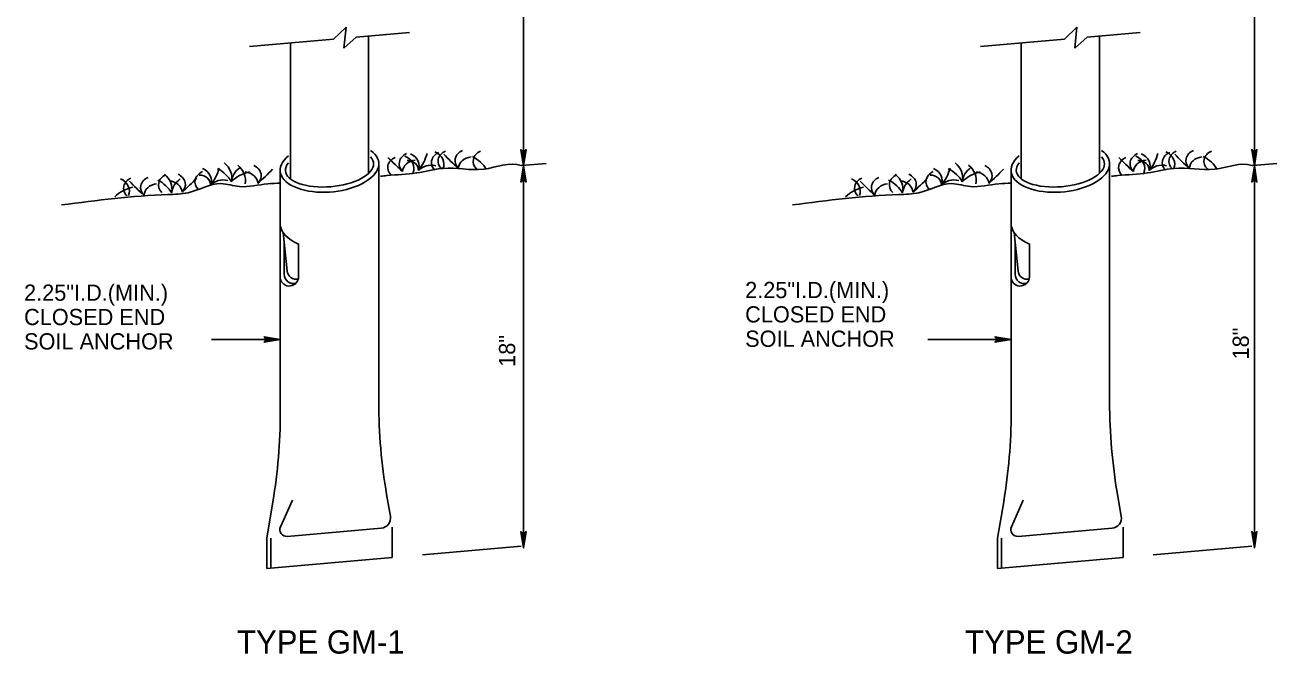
# Model space of a CAD drawing. Extents: x 640253 to 641999, y 298458 to 299646.
# Drawn here: x 640658.7 to 640890, y 299353.4 to 299469.6 of the extents above; entities that cross this region are included whole.
import ezdxf

# ---------------------------------------------------------------- set-up
doc = ezdxf.new("R2010")
doc.units = 0
doc.layers.add('2', color=7, linetype='Continuous')

msp = doc.modelspace()

# ---------------------------------------------------------------- linework, layer by layer
at = {"layer": '2'}
for p, q in [((640750.8, 299443.58), (640750.8, 299512.4)), ((640885.87, 299443.58), (640885.87, 299512.4)), ((640715.71, 299466.98), (640718.01, 299469.2)), ((640718.01, 299469.2), (640717.61, 299465.31)), ((640850.79, 299466.98), (640853.09, 299469.2)), ((640853.09, 299469.2), (640852.69, 299465.31)), ((640700.17, 299465.61), (640715.71, 299466.98)), ((640717.61, 299465.31), (640719.88, 299467.35)), ((640719.88, 299467.35), (640729.7, 299468.21)), ((640722.17, 299467.55), (640722.17, 299442.19)), ((640835.25, 299465.61), (640850.79, 299466.98)), ((640852.69, 299465.31), (640854.96, 299467.35)), ((640854.96, 299467.35), (640864.78, 299468.21)), ((640857.25, 299467.55), (640857.25, 299442.19)), ((640707.71, 299466.28), (640707.71, 299441.18)), ((640842.79, 299466.28), (640842.79, 299441.18)), ((640724.04, 299444.16), (640724.04, 299399.89)), ((640750.5, 299443.61), (640754.97, 299444)), ((640750.8, 299373), (640750.8, 299443.58)), ((640859.12, 299444.16), (640859.12, 299399.89)), ((640885.57, 299443.61), (640890.05, 299444)), ((640885.87, 299373), (640885.87, 299443.58)), ((640705.85, 299442.57), (640705.85, 299398.05)), ((640840.92, 299442.57), (640840.92, 299398.05)), ((640707.11, 299424.14), (640706.38, 299431.28)), ((640842.19, 299424.14), (640841.45, 299431.28)), ((640706.58, 299429.29), (640706.58, 299423.53)), ((640709.23, 299429.14), (640709.23, 299423.08)), ((640841.66, 299429.29), (640841.66, 299423.53)), ((640844.31, 299429.14), (640844.31, 299423.08)), ((640693.12, 299411.48), (640705.85, 299411.48)), ((640825.54, 299411.48), (640840.92, 299411.48)), ((640703.35, 299374.8), (640704.47, 299381.53)), ((640705.88, 299376.89), (640708.08, 299381.83)), ((640726.2, 299378.84), (640725.5, 299382.86)), ((640838.42, 299374.8), (640839.55, 299381.53)), ((640840.96, 299376.89), (640843.16, 299381.83)), ((640861.27, 299378.84), (640860.58, 299382.86)), ((640707.13, 299375.13), (640724.51, 299376.66)), ((640726.54, 299376.84), (640726.54, 299371.21)), ((640842.21, 299375.13), (640859.59, 299376.66)), ((640861.62, 299376.84), (640861.62, 299371.21)), ((640703.35, 299374.8), (640703.35, 299369.18)), ((640704.1, 299374.8), (640704.1, 299369.18)), ((640838.42, 299374.8), (640838.42, 299369.18)), ((640839.17, 299374.8), (640839.17, 299369.18)), ((640732.12, 299371.7), (640750.34, 299373.3)), ((640867.2, 299371.7), (640885.42, 299373.3)), ((640703.35, 299369.18), (640726.54, 299371.21)), ((640838.42, 299369.18), (640861.62, 299371.21))]:
    msp.add_line(p, q, dxfattribs=at)
for points in [[(640751.15, 299446.43), (640750.95, 299446.33), (640750.8, 299443.58), (640751.15, 299446.43), (640751.28, 299446.58), (640750.8, 299443.58), (640750.66, 299446.33), (640750.46, 299446.43), (640750.8, 299443.58), (640750.32, 299446.58), (640750.46, 299446.43)], [(640886.23, 299446.43), (640886.03, 299446.33), (640885.87, 299443.58), (640886.23, 299446.43), (640886.36, 299446.58), (640885.87, 299443.58), (640885.74, 299446.33), (640885.54, 299446.43), (640885.87, 299443.58), (640885.4, 299446.58), (640885.54, 299446.43)], [(640750.44, 299440.73), (640750.64, 299440.83), (640750.8, 299443.58), (640750.44, 299440.73), (640750.31, 299440.58), (640750.8, 299443.58), (640750.93, 299440.83), (640751.14, 299440.73), (640750.8, 299443.58), (640751.27, 299440.58), (640751.14, 299440.73)], [(640885.52, 299440.73), (640885.72, 299440.83), (640885.87, 299443.58), (640885.52, 299440.73), (640885.39, 299440.58), (640885.87, 299443.58), (640886.01, 299440.83), (640886.21, 299440.73), (640885.87, 299443.58), (640886.35, 299440.58), (640886.21, 299440.73)], [(640702.99, 299411.84), (640703.1, 299411.63), (640705.85, 299411.48), (640702.99, 299411.84), (640702.85, 299411.97), (640705.85, 299411.48), (640703.1, 299411.35), (640703, 299411.14), (640705.85, 299411.48), (640702.85, 299411.01), (640703, 299411.14)], [(640838.07, 299411.84), (640838.18, 299411.63), (640840.92, 299411.48), (640838.07, 299411.84), (640837.92, 299411.97), (640840.92, 299411.48), (640838.18, 299411.35), (640838.08, 299411.14), (640840.92, 299411.48), (640837.92, 299411.01), (640838.08, 299411.14)], [(640751.15, 299375.85), (640750.95, 299375.75), (640750.8, 299373), (640751.15, 299375.85), (640751.28, 299376), (640750.8, 299373), (640750.66, 299375.75), (640750.46, 299375.85), (640750.8, 299373), (640750.32, 299376), (640750.46, 299375.85)], [(640886.23, 299375.85), (640886.03, 299375.75), (640885.87, 299373), (640886.23, 299375.85), (640886.36, 299376), (640885.87, 299373), (640885.74, 299375.75), (640885.54, 299375.85), (640885.87, 299373), (640885.4, 299376), (640885.54, 299375.85)]]:
    msp.add_lwpolyline(points, dxfattribs=at)
for centre, radius, start, end in [((640707.52, 299423.08), 1.71, 192.66, 0.0738), ((640708.29, 299423.53), 1.71, 179.9932, 284.9823), ((640708.82, 299424.32), 1.71, 185.8874, 282.1164), ((640842.6, 299423.08), 1.71, 192.66, 0.0738), ((640843.37, 299423.53), 1.71, 179.9932, 284.9823), ((640843.89, 299424.32), 1.71, 185.8874, 282.1164), ((640824.04, 299399.89), 100, 180, 189.8017), ((640959.12, 299399.89), 100, 180, 189.8017), ((640605.85, 299398.04), 100, 350.4939, 0), ((640740.92, 299398.04), 100, 350.4939, 0), ((640724.35, 299378.52), 1.88, 275.0167, 9.777), ((640859.43, 299378.52), 1.88, 275.0167, 9.777), ((640707.02, 299376.38), 1.25, 156.0017, 275.0122), ((640842.1, 299376.38), 1.25, 156.0017, 275.0122)]:
    msp.add_arc(centre, radius, start, end, dxfattribs=at)
for centre, major_axis, ratio, start_param, end_param in [((640714.94, 299443.36), (9.1, 0.8), 0.505377, 2.51251, 6.824211), ((640730.48, 299443.94), (-2.67, 0), 0.81, 5.220291, 6.986898), ((640728.37, 299443.53), (3.17, 0), 0.81, 5.950888, 7.353079), ((640721.23, 299447.88), (12, 0), 0.81, 5.719284, 6.075734), ((640736.45, 299444.15), (-2.67, 0), 0.81, 5.220291, 6.986898), ((640732.91, 299443.89), (3.17, 0), 0.81, 5.950888, 7.353079), ((640737.67, 299444.4), (-2.67, 0), 0.81, 5.220291, 6.986898), ((640768.6, 299465.78), (-40.88, 0), 0.81, 0.65051, 0.753153), ((640740.82, 299444.53), (-2.67, 0), 0.81, 5.220291, 6.986898), ((640744.16, 299444.4), (-2.67, 0), 0.81, 5.220291, 6.986898), ((640850.02, 299443.36), (9.1, 0.8), 0.505377, 2.51251, 6.824211), ((640865.56, 299443.94), (-2.67, 0), 0.81, 5.220291, 6.986898), ((640863.45, 299443.53), (3.17, 0), 0.81, 5.950888, 7.353079), ((640856.31, 299447.88), (12, 0), 0.81, 5.719284, 6.075734), ((640871.52, 299444.15), (-2.67, 0), 0.81, 5.220291, 6.986898), ((640867.99, 299443.89), (3.17, 0), 0.81, 5.950888, 7.353079), ((640872.75, 299444.4), (-2.67, 0), 0.81, 5.220291, 6.986898), ((640903.68, 299465.78), (-40.88, 0), 0.81, 0.65051, 0.753153), ((640875.9, 299444.53), (-2.67, 0), 0.81, 5.220291, 6.986898), ((640879.23, 299444.4), (-2.67, 0), 0.81, 5.220291, 6.986898), ((640691.96, 299441.33), (4.93, 0), 0.81, 6.111626, 7.062961), ((640694.47, 299440.9), (4.93, 0), 0.81, 6.111626, 7.062961), ((640699.66, 299441.74), (2.67, 0), 0.81, 5.579472, 7.346079), ((640714.94, 299443.36), (8.14, 0.71), 0.446872, 2.733251, 5.87413), ((640714.94, 299443.36), (8.14, 0.71), 0.446872, 5.874248, 6.61394), ((640728.37, 299443.25), (-2.67, 0), 0.81, 5.220291, 6.986898), ((640758.27, 299465.19), (-40.88, 0), 0.81, 0.65051, 0.753153), ((640731.2, 299442.43), (-2.76, 0), 0.81, 4.863472, 6.233126), ((640727.37, 299443.11), (3.17, 0), 0.81, 5.950888, 7.353079), ((640729.17, 299442.8), (2.21, 0), 0.81, 6.222188, 7.802691), ((640733.75, 299441.32), (-2.92, 0), 0.81, 4.426104, 5.665423), ((640741.53, 299443.02), (-2.76, 0), 0.81, 4.863472, 6.233126), ((640737.48, 299440.47), (7.12, 0), 0.81, 0.438834, 0.99788), ((640827.04, 299441.33), (4.93, 0), 0.81, 6.111626, 7.062961), ((640829.55, 299440.9), (4.93, 0), 0.81, 6.111626, 7.062961), ((640834.74, 299441.74), (2.67, 0), 0.81, 5.579472, 7.346079), ((640850.02, 299443.36), (8.14, 0.71), 0.446872, 2.733251, 5.87413), ((640850.02, 299443.36), (8.14, 0.71), 0.446872, 5.874248, 6.61394), ((640863.44, 299443.25), (-2.67, 0), 0.81, 5.220291, 6.986898), ((640893.35, 299465.19), (-40.88, 0), 0.81, 0.65051, 0.753153), ((640866.28, 299442.43), (-2.76, 0), 0.81, 4.863472, 6.233126), ((640862.45, 299443.11), (3.17, 0), 0.81, 5.950888, 7.353079), ((640864.25, 299442.8), (2.21, 0), 0.81, 6.222188, 7.802691), ((640868.83, 299441.32), (-2.92, 0), 0.81, 4.426104, 5.665423), ((640876.61, 299443.02), (-2.76, 0), 0.81, 4.863472, 6.233126), ((640872.56, 299440.47), (7.12, 0), 0.81, 0.438834, 0.99788), ((640674.79, 299438.91), (3.17, 0), 0.81, 5.950888, 7.353079), ((640679.55, 299439.42), (-2.67, 0), 0.81, 5.220291, 6.986898), ((640682.7, 299439.55), (-2.67, 0), 0.81, 5.220291, 6.986898), ((640679.33, 299436.11), (7.12, 0), 0.81, 0.438834, 0.99788), ((640686, 299440.04), (-2.67, 0), 0.81, 5.220291, 6.986898), ((640680.91, 299439.24), (4.93, 0), 0.81, 6.111626, 7.062961), ((640690.38, 299438.31), (-4.62, 0), 0.81, 5.422128, 6.217327), ((640685.65, 299440.12), (2.67, 0), 0.81, 5.579472, 7.346079), ((640657.87, 299461.37), (40.88, 0), 0.81, 5.530032, 5.632675), ((640692.75, 299440.62), (-2.67, 0), 0.81, 5.220291, 6.986898), ((640690.75, 299440.09), (2.21, 0), 0.81, 6.222188, 7.802691), ((640689.95, 299440.82), (3.17, 0), 0.81, 5.950888, 7.353079), ((640682.81, 299445.17), (12, 0), 0.81, 5.719284, 6.075734), ((640695.33, 299438.61), (-2.92, 0), 0.81, 4.426104, 5.665423), ((640690.38, 299438.2), (7.12, 0), 0.81, 0.438834, 0.99788), ((640701.43, 299440.4), (-4.62, 0), 0.81, 5.422128, 6.217327), ((640702.01, 299437.27), (-6.66, 0), 0.81, 4.996122, 5.605504), ((640698.94, 299440.23), (2.76, 0), 0.81, 0.050059, 1.419713), ((640671.87, 299462.99), (40.88, 0), 0.81, 5.530032, 5.632675), ((640809.87, 299438.91), (3.17, 0), 0.81, 5.950888, 7.353079), ((640814.63, 299439.42), (-2.67, 0), 0.81, 5.220291, 6.986898), ((640817.77, 299439.55), (-2.67, 0), 0.81, 5.220291, 6.986898), ((640814.41, 299436.11), (7.12, 0), 0.81, 0.438834, 0.99788), ((640821.08, 299440.04), (-2.67, 0), 0.81, 5.220291, 6.986898), ((640815.99, 299439.24), (4.93, 0), 0.81, 6.111626, 7.062961), ((640825.46, 299438.31), (-4.62, 0), 0.81, 5.422128, 6.217327), ((640820.73, 299440.12), (2.67, 0), 0.81, 5.579472, 7.346079), ((640792.95, 299461.37), (40.88, 0), 0.81, 5.530032, 5.632675), ((640827.83, 299440.62), (-2.67, 0), 0.81, 5.220291, 6.986898), ((640825.83, 299440.09), (2.21, 0), 0.81, 6.222188, 7.802691), ((640825.03, 299440.82), (3.17, 0), 0.81, 5.950888, 7.353079), ((640817.89, 299445.17), (12, 0), 0.81, 5.719284, 6.075734), ((640830.41, 299438.61), (-2.92, 0), 0.81, 4.426104, 5.665423), ((640825.45, 299438.2), (7.12, 0), 0.81, 0.438834, 0.99788), ((640836.51, 299440.4), (-4.62, 0), 0.81, 5.422128, 6.217327), ((640837.08, 299437.27), (-6.66, 0), 0.81, 4.996122, 5.605504), ((640834.02, 299440.23), (2.76, 0), 0.81, 0.050059, 1.419713), ((640806.95, 299462.99), (40.88, 0), 0.81, 5.530032, 5.632675), ((640680.44, 299434.45), (-6.66, 0), 0.81, 4.996122, 5.605504), ((640710.48, 299460.8), (-40.88, 0), 0.81, 0.65051, 0.753153), ((640683.41, 299438.04), (-2.76, 0), 0.81, 4.863472, 6.233126), ((640684.94, 299438.61), (2.76, 0), 0.81, 0.050059, 1.419713), ((640815.52, 299434.45), (-6.66, 0), 0.81, 4.996122, 5.605504), ((640845.56, 299460.8), (-40.88, 0), 0.81, 0.65051, 0.753153), ((640818.49, 299438.04), (-2.76, 0), 0.81, 4.863472, 6.233126), ((640820.02, 299438.61), (2.76, 0), 0.81, 0.050059, 1.419713), ((640716.76, 299433.65), (10.92, 0.96), 0.505377, 3.143506, 3.907964), ((640851.84, 299433.65), (10.92, 0.96), 0.505377, 3.143506, 3.907964)]:
    msp.add_ellipse(centre, major_axis=major_axis, ratio=ratio, start_param=start_param, end_param=end_param, dxfattribs=at)
for points in [[(640724.38, 299441.66), (640725.56, 299441.78), (640731.03, 299442.26), (640735.93, 299443.11), (640743.46, 299442.97), (640750.39, 299443.64), (640750.51, 299443.6)], [(640859.46, 299441.66), (640860.64, 299441.78), (640866.11, 299442.26), (640871.01, 299443.11), (640878.54, 299442.97), (640885.46, 299443.64), (640885.59, 299443.6)], [(640665.43, 299436.35), (640685.08, 299438.26), (640688.79, 299438.6), (640694.87, 299440.29), (640698.3, 299439.75), (640703.54, 299440.26), (640705.85, 299440.36)], [(640800.5, 299436.35), (640820.15, 299438.26), (640823.87, 299438.6), (640829.95, 299440.29), (640833.38, 299439.75), (640838.62, 299440.26), (640840.92, 299440.36)]]:
    msp.add_spline(points, degree=3, dxfattribs=at)

# ---------------------------------------------------------------- texts
for s, height, p in [('2.25"I.D.(MIN.)', 3, (640658.49, 299418.65)), ('2.25"I.D.(MIN.)', 3, (640791.76, 299419.14)), ('CLOSED END', 3, (640658.49, 299414.15)), ('CLOSED END', 3, (640791.76, 299414.64)), ('SOIL ANCHOR', 3, (640791.76, 299410.14)), ('SOIL ANCHOR', 3, (640658.49, 299409.65)), ('TYPE GM-1', 4.3, (640697.84, 299353.47)), ('TYPE GM-2', 4.3, (640832.41, 299353.47))]:
    msp.add_text(s, height=height, dxfattribs=at).set_placement(p)
for p in [(640884.86, 299407.8), (640749.26, 299406.44)]:
    msp.add_text('18"', height=3, rotation=90, dxfattribs=at).set_placement(p)

doc.saveas('drawing.dxf')
